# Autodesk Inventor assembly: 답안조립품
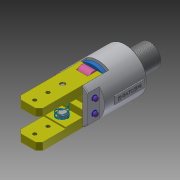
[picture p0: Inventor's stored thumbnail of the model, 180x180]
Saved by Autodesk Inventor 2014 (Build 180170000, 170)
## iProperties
Created: 2019-02
Part Number: 답안조립품
Document SubType Name: Assembly
Designer: OA55
Author: OA55
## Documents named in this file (11)
- C:\Users\OA55\Desktop\490208V1003\답안조립품.iam
- C:\Users\OA55\Desktop\490208V1003\본체.ipt
- C:\Users\OA55\Desktop\490208V1003\피스톤.ipt
- C:\Users\OA55\Desktop\490208V1003\핑거.ipt
- C:\Users\OA55\Desktop\490208V1003\부시.ipt
- C:\Users\OA55\Desktop\490208V1003\평행핀 6x28.ipt
- C:\Users\OA55\Desktop\490208V1003\핀.ipt
- C:\Users\OA55\Desktop\490208V1003\E-링.ipt
- C:\Users\OA55\Desktop\490208V1003\가이드핀.ipt
- C:\Users\OA55\Desktop\490208V1003\스프링.ipt
- C:\Users\OA55\Desktop\490208V1003\O-링.ipt
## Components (13 placed, 6 different names)
1. 피스톤:1
2. 핑거:1 — 각도:1
3. 핑거:2 — 각도:2
4. 핀:1
5. 핀:2
6. E-링:1
7. E-링:2
8. E-링:3
9. E-링:4
10. 가이드핀:1
11. 가이드핀:2
12. O-링:1
13. O-링:2
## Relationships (2: Angle 2)
- 각도:1 [Angle]: 핑거:1
- 각도:2 [Angle]: 핑거:2
